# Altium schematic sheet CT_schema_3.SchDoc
size 521 x 498 mm
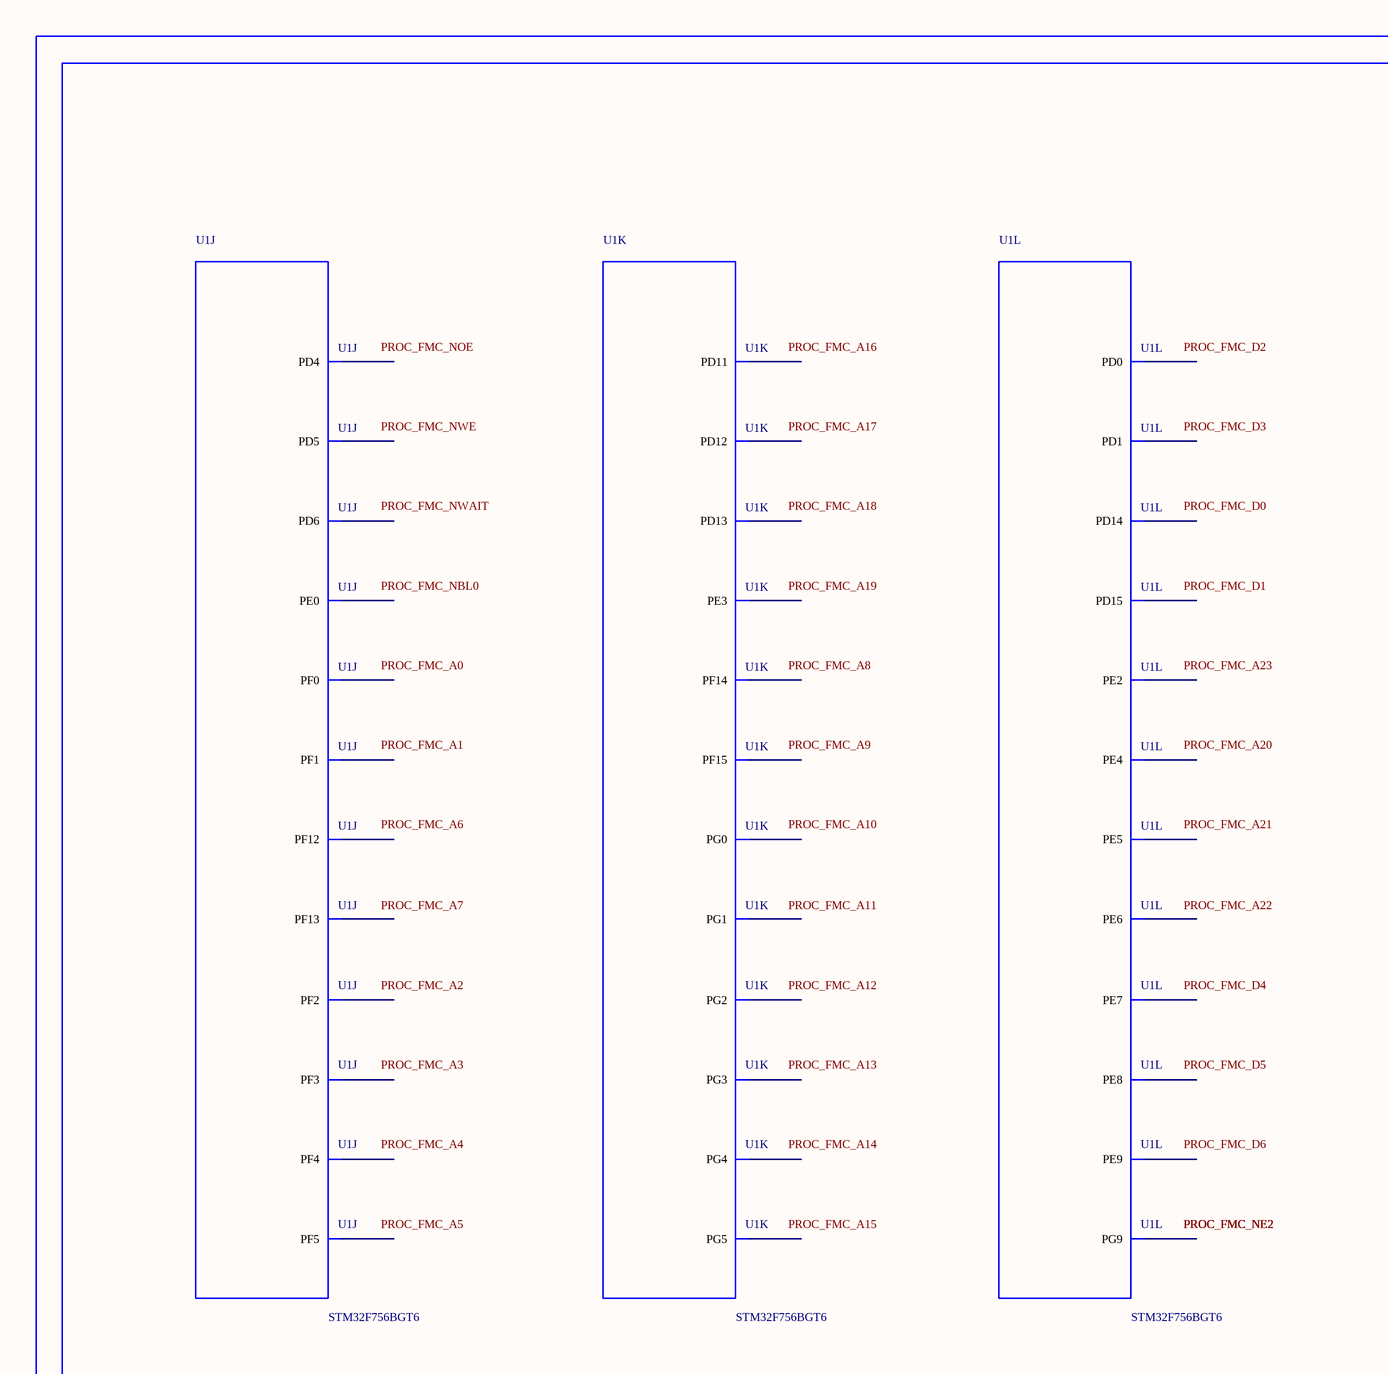
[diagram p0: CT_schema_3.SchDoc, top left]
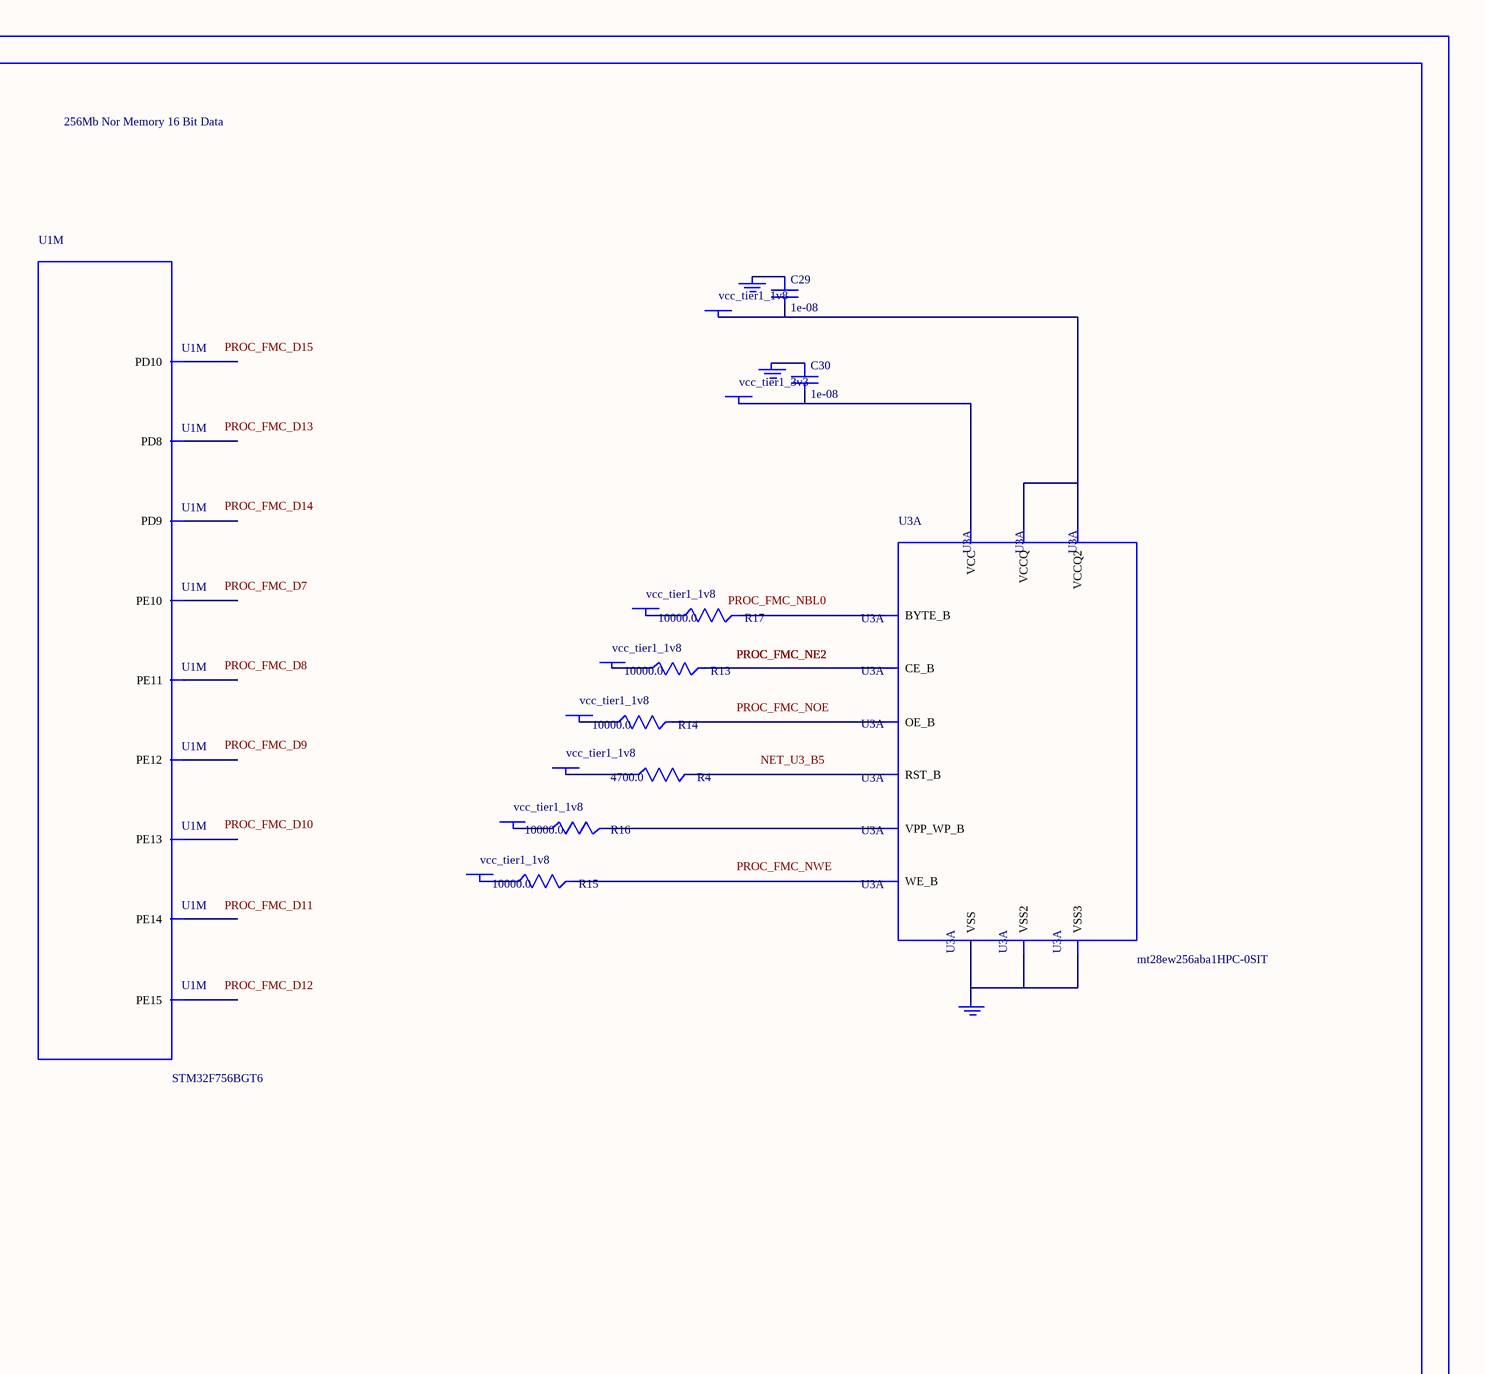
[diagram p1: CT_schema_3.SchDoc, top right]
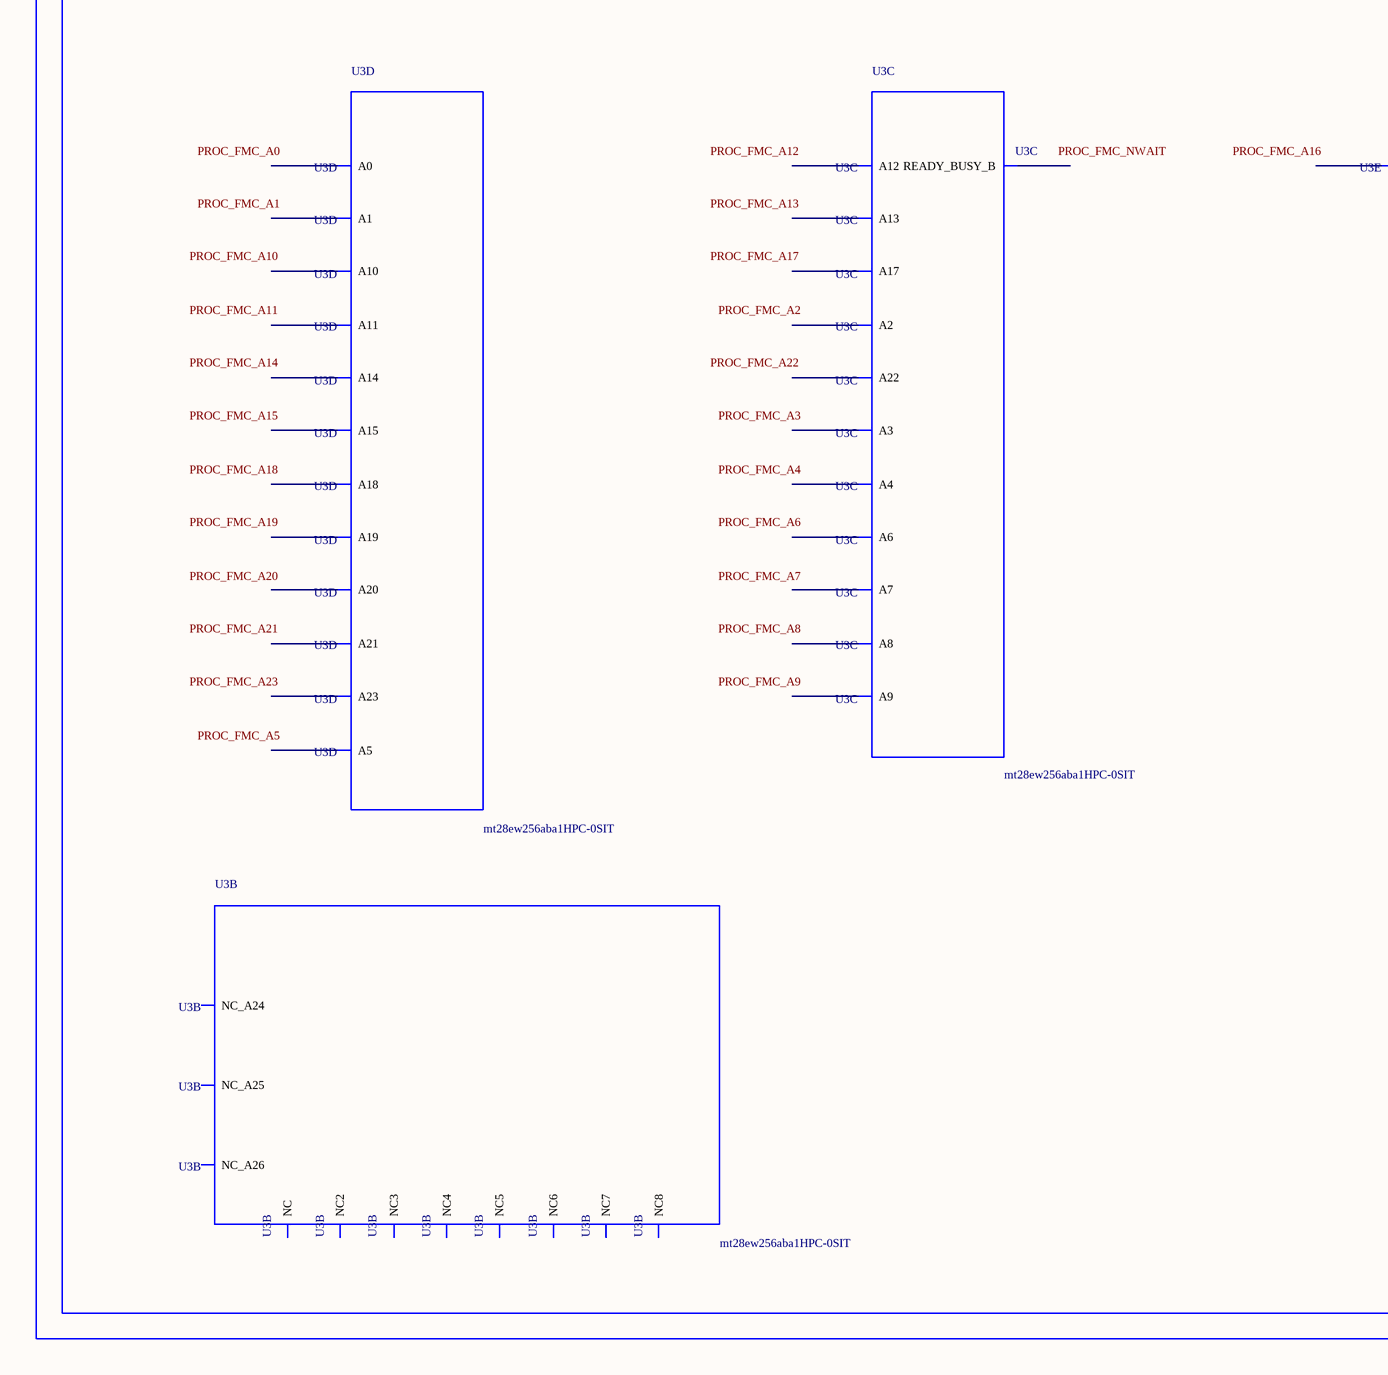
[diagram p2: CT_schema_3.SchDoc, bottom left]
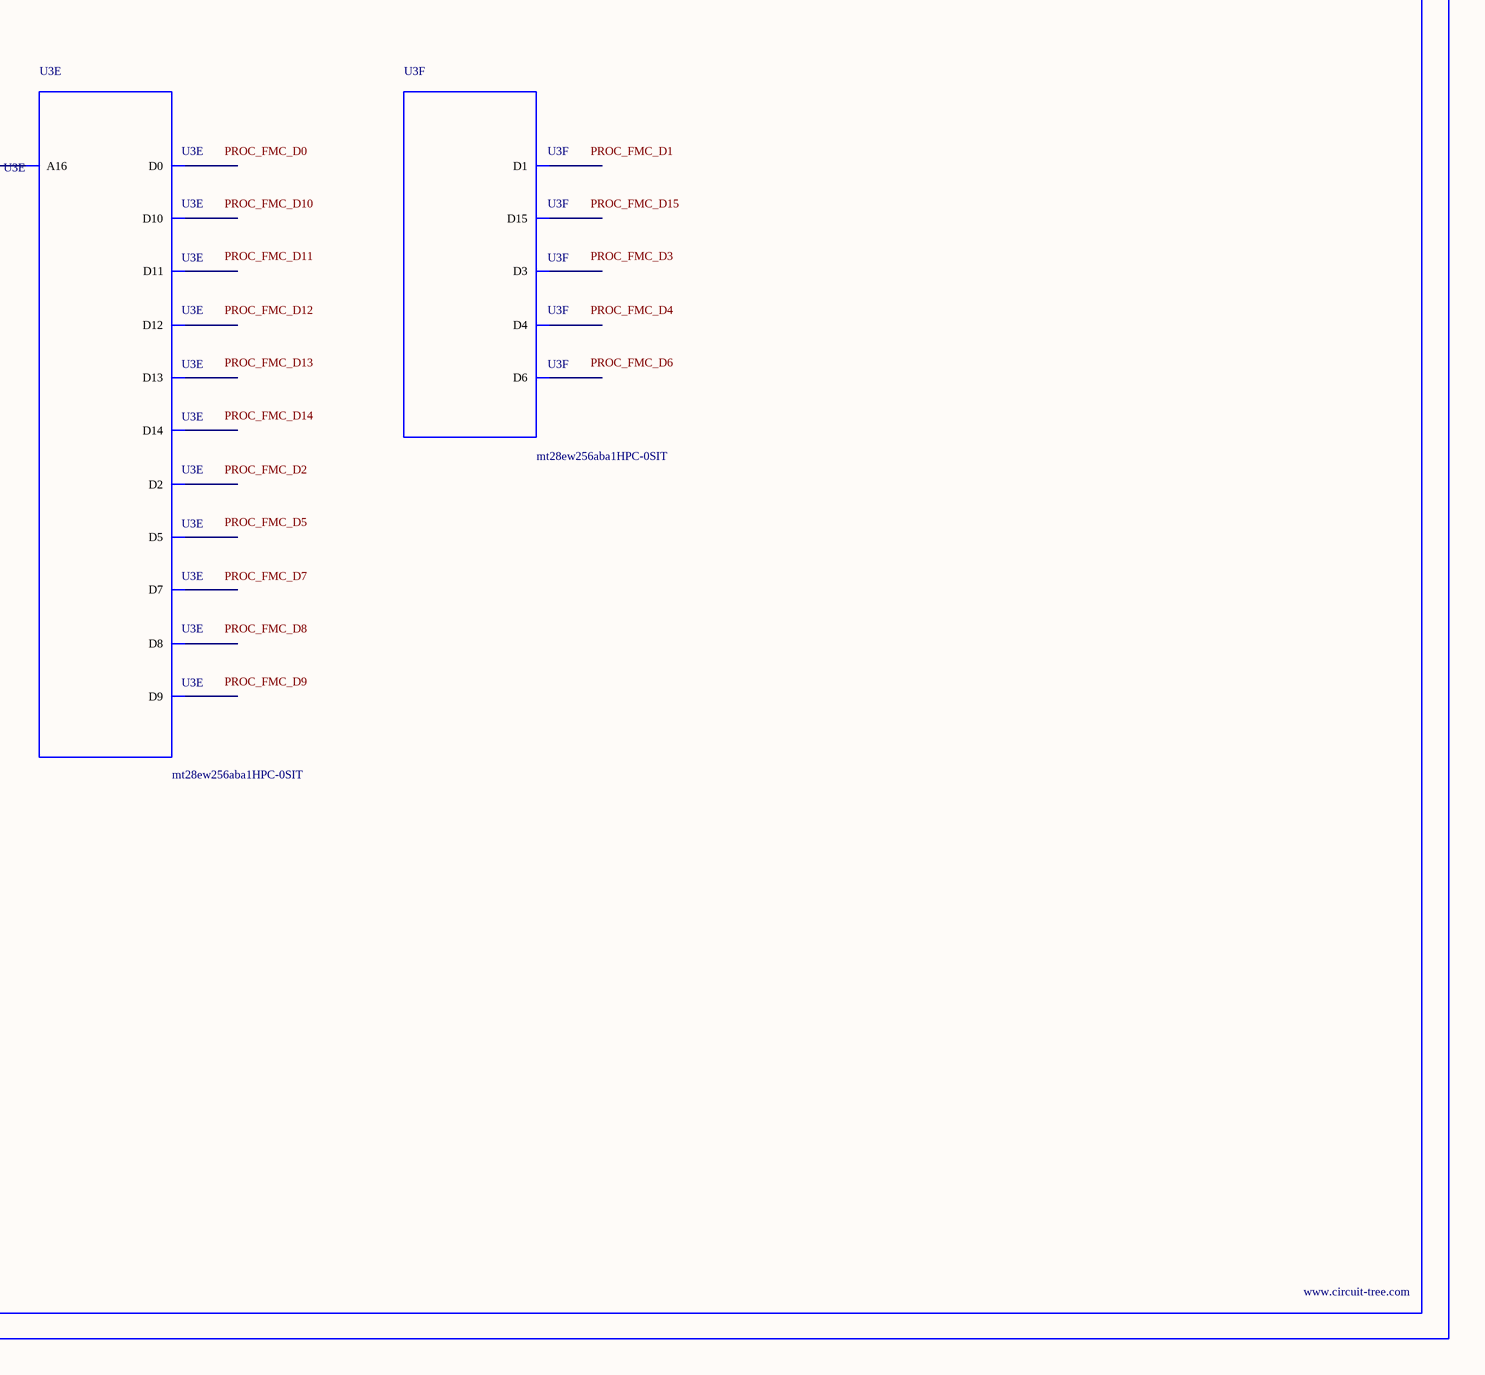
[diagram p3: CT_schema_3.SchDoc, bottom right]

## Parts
BORDER2  (no value)
C29  1e-08  [C0402]
C30  1e-08  [C0402]
GND_INSTANCE_2_0  (no value)
GND_INSTANCE_2_1  (no value)
GND_INSTANCE_2_2  (no value)
POWER_INSTANCE_2_0  vcc_tier1_1v8
POWER_INSTANCE_2_1  vcc_tier1_3v3
POWER_INSTANCE_2_2  vcc_tier1_1v8
POWER_INSTANCE_2_3  vcc_tier1_1v8
POWER_INSTANCE_2_4  vcc_tier1_1v8
POWER_INSTANCE_2_5  vcc_tier1_1v8
POWER_INSTANCE_2_6  vcc_tier1_1v8
POWER_INSTANCE_2_7  vcc_tier1_1v8
R4  4700.0  [R0603]
R13  10000.0  [R0603]
R14  10000.0  [R0603]
R15  10000.0  [R0603]
R16  10000.0  [R0603]
R17  10000.0  [R0603]
U1  STM32F756BGT6  [LQFP208]  (parts J,K,L,M of 15)
U3  mt28ew256aba1HPC-0SIT  [LBGA-64]  (parts A,B,C,D,E,F of 6)

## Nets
NetC29_1: C29.1 GND_INSTANCE_2_0.0(GND)
NetC29_2: C29.2 POWER_INSTANCE_2_0.0(PWR) U3.D8(VCCQ) U3.F1(VCCQ2)
NetC30_1: C30.1 GND_INSTANCE_2_1.0(GND)
NetC30_2: C30.2 POWER_INSTANCE_2_1.0(PWR) U3.G5(VCC)
NetGND_INSTANCE_2_2_0: GND_INSTANCE_2_2.0(GND) U3.E8(VSS) U3.H2(VSS2) U3.H7(VSS3)
NetPOWER_INSTANCE_2_2_0: POWER_INSTANCE_2_2.0(PWR) R13.1
NetPOWER_INSTANCE_2_3_0: POWER_INSTANCE_2_3.0(PWR) R14.1
NetPOWER_INSTANCE_2_4_0: POWER_INSTANCE_2_4.0(PWR) R15.1
NetPOWER_INSTANCE_2_5_0: POWER_INSTANCE_2_5.0(PWR) R16.1
NetPOWER_INSTANCE_2_6_0: POWER_INSTANCE_2_6.0(PWR) R17.1
NetPOWER_INSTANCE_2_7_0: POWER_INSTANCE_2_7.0(PWR) R4.1
NetR4_2: R4.2 U3.B5(RST_B)
NetR13_2: R13.2 U3.F2(CE_B)
NetR14_2: R14.2 U3.G2(OE_B)
NetR15_2: R15.2 U3.A5(WE_B)
NetR16_2: R16.2 U3.B4(VPP_WP_B)
NetR17_2: R17.2 U3.F7(BYTE_B)

Not connected (* = marked no-connect by the designer): U1 1(PE2) 2(PE3) 3(PE4) 4(PE5) 5(PE6) 16(PF0) 17(PF1) 18(PF2) 22(PF3) 23(PF4) 24(PF5) 71(PF12) 74(PF13) 75(PF14) 76(PF15) 77(PG0) 78(PG1) 79(PE7) 80(PE8) 81(PE9) 84(PE10) 85(PE11) 86(PE12) 87(PE13) 88(PE14) 89(PE15) 108(PD8) 109(PD9) 110(PD10) 111(PD11) 112(PD12) 113(PD13) 116(PD14) 117(PD15) 129(PG2) 130(PG3) 131(PG4) 132(PG5) 164(PD0) 165(PD1) 168(PD4) 169(PD5) 172(PD6) 178(PG9) 200(PE0); U3 A1(NC) A2(A3) A3(A7) A4(READY_BUSY_B) A6(A9) A7(A13) A8(NC2) B1(NC_A26) B2(A4) B3(A17) B6(A8) B7(A12) B8(A22) C1(NC3) C2(A2) C3(A6) C4(A18) C5(A21) C6(A10) C7(A14) C8(A23) D1(NC4) D2(A1) D3(A5) D4(A20) D5(A19) D6(A11) D7(A15) E1(NC5) E2(A0) E3(D0) E4(D2) E5(D5) E6(D7) E7(A16) F3(D8) F4(D10) F5(D12) F6(D14) F8(NC_A24) G1(NC6) G3(D9) G4(D11) G6(D13) G7(D15) G8(NC_A25) H1(NC7) H3(D1) H4(D3) H5(D4) H6(D6) H8(NC8)

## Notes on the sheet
- Labels drawn without touching a wire or pin: NET_U3_B5, PROC_FMC_A0, PROC_FMC_A1, PROC_FMC_A2, PROC_FMC_A3, PROC_FMC_A4, PROC_FMC_A5, PROC_FMC_A6, PROC_FMC_A7, PROC_FMC_A8, PROC_FMC_A9, PROC_FMC_A10, PROC_FMC_A11, PROC_FMC_A12, PROC_FMC_A13, PROC_FMC_A14, PROC_FMC_A15, PROC_FMC_A16, PROC_FMC_A17, PROC_FMC_A18, PROC_FMC_A19, PROC_FMC_A20, PROC_FMC_A21, PROC_FMC_A22, PROC_FMC_A23, PROC_FMC_D0, PROC_FMC_D1, PROC_FMC_D2, PROC_FMC_D3, PROC_FMC_D4, PROC_FMC_D5, PROC_FMC_D6, PROC_FMC_D7, PROC_FMC_D8, PROC_FMC_D9, PROC_FMC_D10, PROC_FMC_D11, PROC_FMC_D12, PROC_FMC_D13, PROC_FMC_D14, PROC_FMC_D15, PROC_FMC_NBL0, PROC_FMC_NOE, PROC_FMC_NWAIT, PROC_FMC_NWE

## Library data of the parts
BORDER2 = BORDER_PAGE2
C29 C30 = C0402C103K3RAC
GND_INSTANCE_2_0-GND_INSTANCE_2_2 = GND
POWER_INSTANCE_2_0-POWER_INSTANCE_2_7 = PWR
R4 = RC0603JR-074K7L
R13-R17 = RC0603JR-0710KL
